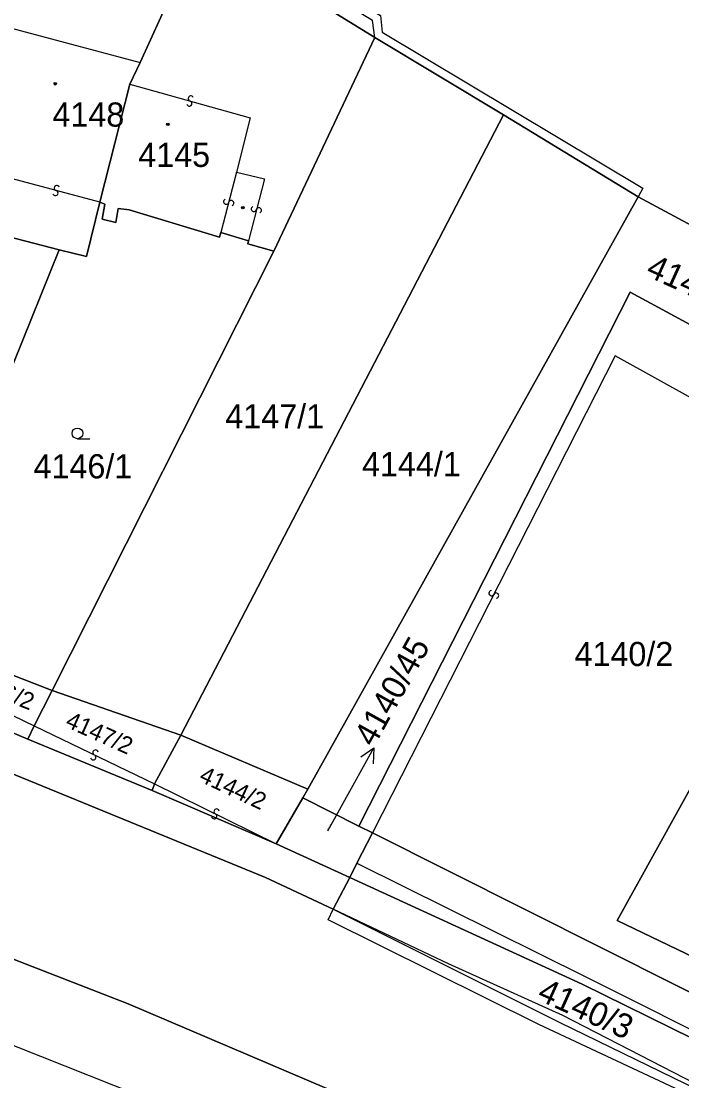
# Model space of a CAD drawing. Extents: x -598233 to -596890, y -1157848 to -1156431.
# Drawn here: x -597287.6 to -597241.1, y -1157710 to -1157635.4 of the extents above; entities that cross this region are included whole.
import ezdxf

# ---------------------------------------------------------------- set-up
doc = ezdxf.new("R2010")
doc.units = 0
for name, color, linetype in [('Level 1', 7, 'Continuous'), ('Level 13', 7, 'Continuous'), ('Level 3', 7, 'Continuous'), ('Level 4', 7, 'Continuous'), ('Level 5', 7, 'Continuous'), ('Level 57', 7, 'Continuous'), ('Level 60', 7, 'Continuous'), ('Vrstva 60', 7, 'Continuous')]:
    doc.layers.add(name, color=color, linetype=linetype)

msp = doc.modelspace()

# ---------------------------------------------------------------- linework, layer by layer
at = {"layer": 'Level 1'}
for points in [[(-597274.42, -1157629.37), (-597275.18, -1157629), (-597277.83, -1157635.13), (-597279.27, -1157638.34)], [(-597274.42, -1157629.37), (-597262.75, -1157636.58)], [(-597269.86, -1157651.62), (-597262.75, -1157636.58)], [(-597262.75, -1157636.58), (-597253.7, -1157642.01)], [(-597279.99, -1157639.86), (-597279.27, -1157638.34)], [(-597282.11, -1157648.18), (-597279.99, -1157639.86)], [(-597436.18, -1157640.9), (-597423.8, -1157643.87), (-597403.31, -1157649.2), (-597374.8, -1157657.21), (-597357.42, -1157662.9), (-597326.65, -1157673.96), (-597297.15, -1157684.79), (-597270.46, -1157695.74), (-597265.69, -1157697.96)], [(-597276.42, -1157685.7), (-597253.7, -1157642.01)], [(-597253.7, -1157642.01), (-597244.22, -1157647.79)], [(-597284.97, -1157651.52), (-597300.24, -1157647.57)], [(-597284.97, -1157651.52), (-597283.06, -1157651.99), (-597282.11, -1157648.18)], [(-597273.6, -1157650.31), (-597273.69, -1157650.63), (-597280.06, -1157648.71), (-597280.83, -1157648.62), (-597280.98, -1157649.61), (-597281.95, -1157649.36), (-597281.75, -1157648.3), (-597282.11, -1157648.18)], [(-597267.47, -1157689.5), (-597244.22, -1157647.79)], [(-597244.22, -1157647.79), (-597223.6, -1157658.88)], [(-597271.66, -1157650.89), (-597273.6, -1157650.31)], [(-597269.86, -1157651.62), (-597271.69, -1157651.11), (-597271.66, -1157650.89)], [(-597291.44, -1157667.49), (-597284.97, -1157651.52)], [(-597285.48, -1157682.57), (-597269.86, -1157651.62)], [(-597226.62, -1157664.34), (-597244.78, -1157654.52), (-597263.89, -1157692.11)], [(-597228.87, -1157668.41), (-597245.7, -1157698.76), (-597224.61, -1157708.91)], [(-597285.48, -1157682.57), (-597292.8, -1157679.73)], [(-597286.73, -1157685.05), (-597285.48, -1157682.57)], [(-597276.42, -1157685.7), (-597285.48, -1157682.57)], [(-597287.17, -1157685.98), (-597294.12, -1157683.06)], [(-597287.17, -1157685.98), (-597286.73, -1157685.05)], [(-597278.26, -1157689.14), (-597276.42, -1157685.7)], [(-597267.47, -1157689.5), (-597276.42, -1157685.7)], [(-597278.44, -1157689.6), (-597287.17, -1157685.98)], [(-597206.41, -1157739.84), (-597260.41, -1157713.03), (-597280.11, -1157704.64), (-597306.45, -1157694.39), (-597321.34, -1157688.54)], [(-597278.44, -1157689.6), (-597278.26, -1157689.14)], [(-597267.83, -1157690.13), (-597267.47, -1157689.5)], [(-597269.69, -1157693.35), (-597278.44, -1157689.6)], [(-597269.69, -1157693.35), (-597267.83, -1157690.13)], [(-597267.83, -1157690.13), (-597263.89, -1157692.11)], [(-597263.89, -1157692.11), (-597262.93, -1157692.59)], [(-597262.93, -1157692.59), (-597264.02, -1157694.72)], [(-597262.93, -1157692.59), (-597203.85, -1157722.25)], [(-597323.49, -1157693.63), (-597308.23, -1157699.6), (-597274.42, -1157713.03), (-597265.13, -1157717.22)], [(-597264.52, -1157695.72), (-597269.69, -1157693.35)], [(-597264.02, -1157694.72), (-597264.52, -1157695.72)], [(-597265.69, -1157697.96), (-597264.52, -1157695.72)], [(-597264.52, -1157695.72), (-597248.17, -1157703.24), (-597226.43, -1157713.96), (-597204.86, -1157724.29)], [(-597203.17, -1157729.43), (-597220.64, -1157720.4), (-597251.21, -1157706.08), (-597266.03, -1157698.72), (-597265.69, -1157697.96)]]:
    msp.add_lwpolyline(points, dxfattribs=at)
at = {"layer": 'Level 13'}
for centre, start, end in [((-597275.708, -1157640.873), 21.66017, 253.75817), ((-597275.811, -1157641.227), 201.44572, 74.03572), ((-597285.24, -1157647.528), 202.2675, 74.3655), ((-597285.141, -1157647.173), 22.05304, 254.64304), ((-597273.218, -1157648.133), 112.55383, 345.14383), ((-597272.862, -1157648.228), 292.76829, 164.86628), ((-597271.278, -1157648.653), 112.66023, 345.25023), ((-597270.922, -1157648.748), 292.87469, 164.97268), ((-597254.544, -1157675.706), 100.19898, 332.78898), ((-597254.216, -1157675.875), 280.41344, 152.51143), ((-597282.581, -1157687.265), 191.38328, 63.97328), ((-597282.418, -1157686.935), 11.59773, 243.69573), ((-597273.897, -1157691.085), 11.21022, 243.30822), ((-597274.062, -1157691.415), 190.99577, 63.58577)]:
    msp.add_arc(centre, 0.184, start, end, dxfattribs=at)
at = {"layer": 'Level 3'}
for points in [[(-597287.53, -1157622.17), (-597303.98, -1157613.97), (-597304.26, -1157614.64), (-597304.71, -1157614.38), (-597304.16, -1157613.27), (-597287.27, -1157621.7), (-597286.54, -1157620.31), (-597262.36, -1157635.02), (-597262.23, -1157636.2), (-597243.89, -1157647.18), (-597244.22, -1157647.79)], [(-597262.75, -1157636.58), (-597262.93, -1157635.38), (-597274.03, -1157628.64)], [(-597289.97, -1157646.1), (-597290.84, -1157645.84), (-597288.32, -1157635.92), (-597279.27, -1157638.34)], [(-597279.99, -1157639.86), (-597271.53, -1157642.24), (-597272.49, -1157646.05)], [(-597272.49, -1157646.05), (-597273.6, -1157650.31)], [(-597272.49, -1157646.05), (-597270.53, -1157646.52), (-597271.66, -1157650.89)], [(-597282.11, -1157648.18), (-597288.26, -1157646.52)], [(-597228.87, -1157668.41), (-597245.84, -1157658.99), (-597262.93, -1157692.59)], [(-597293.58, -1157681.74), (-597286.73, -1157685.05)], [(-597286.73, -1157685.05), (-597278.26, -1157689.14)], [(-597278.26, -1157689.14), (-597269.69, -1157693.35)], [(-597264.02, -1157694.72), (-597247.9, -1157702.73), (-597204.86, -1157724.29)], [(-597228.48, -1157716.29), (-597249.52, -1157705.44), (-597257.57, -1157701.81), (-597265.69, -1157697.96)], [(-597265.69, -1157697.96), (-597249.74, -1157705.94), (-597228.48, -1157716.29)]]:
    msp.add_lwpolyline(points, dxfattribs=at)
at = {"layer": 'Level 5'}
msp.add_line((-597283.69, -1157664.83), (-597282.815, -1157664.83), dxfattribs=at)
for centre, radius in [((-597285.25, -1157639.83), 0.09), ((-597285.25, -1157639.83), 0.0521), ((-597277.33, -1157642.69), 0.09), ((-597277.33, -1157642.69), 0.0521), ((-597272.05, -1157648.56), 0.09), ((-597272.05, -1157648.56), 0.0521), ((-597283.69, -1157664.455), 0.375)]:
    msp.add_circle(centre, radius, dxfattribs=at)
at = {"layer": 'Level 57'}
for p, q in [((-597264.282, -1157689.234), (-597262.827, -1157686.611)), ((-597266.06, -1157692.44), (-597264.282, -1157689.234))]:
    msp.add_line(p, q, dxfattribs=at)
msp.add_lwpolyline([(-597263.749, -1157687.242), (-597262.827, -1157686.611), (-597262.875, -1157687.728)], dxfattribs=at)
at = {"layer": 'Level 60'}
for points in [[(-597105.48, -1157726.35), (-597142.21, -1157703.35), (-597142.63, -1157703.09), (-597163.36, -1157691.81), (-597183.34, -1157680.94), (-597203.62, -1157669.9), (-597204.01, -1157669.69), (-597223.6, -1157658.88), (-597244.22, -1157647.79), (-597253.7, -1157642.01), (-597262.75, -1157636.58), (-597274.42, -1157629.37), (-597274.03, -1157628.64), (-597275.33, -1157627.77), (-597275.92, -1157628.88), (-597286.84, -1157621.88), (-597287.53, -1157622.17), (-597287.76, -1157622.64), (-597288.14, -1157622.45), (-597304.52, -1157615.14), (-597305.39, -1157615), (-597306.09, -1157615.82), (-597336.02, -1157596.93), (-597343.31, -1157592.43)], [(-597356.03, -1157660.15), (-597325.9, -1157671.16), (-597312.06, -1157676.28), (-597298.62, -1157681.23), (-597297.23, -1157681.78), (-597294.12, -1157683.06), (-597287.17, -1157685.98), (-597278.44, -1157689.6), (-597269.69, -1157693.35), (-597264.52, -1157695.72), (-597265.69, -1157697.96), (-597270.46, -1157695.74), (-597297.15, -1157684.79), (-597326.65, -1157673.96), (-597357.42, -1157662.9)]]:
    msp.add_lwpolyline(points, dxfattribs=at)
for points in [[(-597274.42, -1157629.37), (-597275.18, -1157629), (-597277.83, -1157635.13), (-597279.27, -1157638.34), (-597279.99, -1157639.86), (-597282.11, -1157648.18), (-597283.06, -1157651.99), (-597284.97, -1157651.52), (-597300.24, -1157647.57), (-597292.3, -1157628.34), (-597291.08, -1157628.87), (-597288.38, -1157622.79), (-597288.14, -1157622.45), (-597287.76, -1157622.64), (-597287.53, -1157622.17), (-597286.84, -1157621.88), (-597275.92, -1157628.88), (-597275.33, -1157627.77), (-597274.03, -1157628.64)], [(-597262.75, -1157636.58), (-597269.86, -1157651.62), (-597271.69, -1157651.11), (-597271.66, -1157650.89), (-597273.6, -1157650.31), (-597273.69, -1157650.63), (-597280.06, -1157648.71), (-597280.83, -1157648.62), (-597280.98, -1157649.61), (-597281.95, -1157649.36), (-597281.75, -1157648.3), (-597282.11, -1157648.18), (-597279.99, -1157639.86), (-597279.27, -1157638.34), (-597277.83, -1157635.13), (-597275.18, -1157629), (-597274.42, -1157629.37)], [(-597253.7, -1157642.01), (-597276.42, -1157685.7), (-597285.48, -1157682.57), (-597269.86, -1157651.62), (-597262.75, -1157636.58)], [(-597244.22, -1157647.79), (-597267.47, -1157689.5), (-597276.42, -1157685.7), (-597253.7, -1157642.01)], [(-597284.97, -1157651.52), (-597291.44, -1157667.49), (-597291.61, -1157667.24), (-597293.49, -1157669.57), (-597294.74, -1157672.51), (-597295.44, -1157674.7), (-597298.57, -1157671.87), (-597303.64, -1157669.17), (-597306.37, -1157674.04), (-597310.49, -1157672.49), (-597300.24, -1157647.57)], [(-597269.86, -1157651.62), (-597285.48, -1157682.57), (-597292.8, -1157679.73), (-597295.87, -1157678.53), (-597295.68, -1157678.06), (-597291.44, -1157667.49), (-597284.97, -1157651.52), (-597283.06, -1157651.99), (-597282.11, -1157648.18), (-597281.75, -1157648.3), (-597281.95, -1157649.36), (-597280.98, -1157649.61), (-597280.83, -1157648.62), (-597280.06, -1157648.71), (-597273.69, -1157650.63), (-597273.6, -1157650.31), (-597271.66, -1157650.89), (-597271.69, -1157651.11)], [(-597244.22, -1157647.79), (-597223.6, -1157658.88), (-597226.62, -1157664.34), (-597244.78, -1157654.52), (-597263.89, -1157692.11), (-597267.83, -1157690.13), (-597267.47, -1157689.5)], [(-597244.78, -1157654.52), (-597226.62, -1157664.34), (-597228.87, -1157668.41), (-597245.7, -1157698.76), (-597224.61, -1157708.91), (-597223.9, -1157709.25), (-597223.46, -1157708.39), (-597202.15, -1157718.82), (-597203.85, -1157722.25), (-597262.93, -1157692.59), (-597263.89, -1157692.11)], [(-597245.7, -1157698.76), (-597228.87, -1157668.41), (-597226.62, -1157664.34), (-597206.82, -1157675.05), (-597209.1, -1157679.38), (-597224.61, -1157708.91)], [(-597286.73, -1157685.05), (-597287.17, -1157685.98), (-597294.12, -1157683.06), (-597297.23, -1157681.78), (-597295.87, -1157678.53), (-597292.8, -1157679.73), (-597285.48, -1157682.57)], [(-597278.26, -1157689.14), (-597278.44, -1157689.6), (-597287.17, -1157685.98), (-597286.73, -1157685.05), (-597285.48, -1157682.57), (-597276.42, -1157685.7)], [(-597276.42, -1157685.7), (-597267.47, -1157689.5), (-597267.83, -1157690.13), (-597269.69, -1157693.35), (-597278.44, -1157689.6), (-597278.26, -1157689.14)], [(-597263.89, -1157692.11), (-597262.93, -1157692.59), (-597264.02, -1157694.72), (-597264.52, -1157695.72), (-597269.69, -1157693.35), (-597267.83, -1157690.13)], [(-597248.17, -1157703.24), (-597264.52, -1157695.72), (-597264.02, -1157694.72), (-597262.93, -1157692.59), (-597203.85, -1157722.25), (-597204.86, -1157724.29), (-597226.43, -1157713.96)], [(-597308.23, -1157699.6), (-597274.42, -1157713.03), (-597265.13, -1157717.22), (-597266.49, -1157735.43), (-597266.77, -1157739.16), (-597271.23, -1157798.83), (-597271.44, -1157801.64), (-597271.69, -1157804.95), (-597272.23, -1157804.82), (-597267.63, -1157744.82), (-597279.67, -1157743.88), (-597284.24, -1157803.9), (-597302.09, -1157802.66), (-597301.45, -1157792.4), (-597337.11, -1157790.23), (-597333.99, -1157744.43), (-597331.01, -1157701.76), (-597330.83, -1157696.39), (-597329.58, -1157696.52), (-597323.49, -1157693.63)], [(-597200.42, -1157730.59), (-597203.17, -1157729.43), (-597220.64, -1157720.4), (-597251.21, -1157706.08), (-597266.03, -1157698.72), (-597265.69, -1157697.96), (-597264.52, -1157695.72), (-597248.17, -1157703.24), (-597226.43, -1157713.96), (-597204.86, -1157724.29), (-597201.45, -1157726), (-597196.19, -1157729.11), (-597196.52, -1157729.66), (-597196.97, -1157730.19), (-597197.74, -1157730.69), (-597198.63, -1157730.94), (-597199.55, -1157730.91)]]:
    msp.add_lwpolyline(points, close=True, dxfattribs=at)
at = {"layer": 'Vrstva 60'}
for points in [[(-597117.85, -1157772.55), (-597172.78, -1157744.55), (-597189.92, -1157735.64), (-597200.42, -1157730.59), (-597203.17, -1157729.43), (-597220.64, -1157720.4), (-597251.21, -1157706.08), (-597266.03, -1157698.72), (-597265.69, -1157697.96), (-597270.46, -1157695.74), (-597297.15, -1157684.79), (-597326.65, -1157673.96), (-597357.42, -1157662.9), (-597374.8, -1157657.21), (-597403.31, -1157649.2), (-597423.8, -1157643.87), (-597436.18, -1157640.9), (-597457.3, -1157637.23), (-597508.21, -1157627.05), (-597565.01, -1157615.5), (-597619.03, -1157604.22), (-597671.31, -1157593.83)], [(-597674.27, -1157604.65), (-597621.93, -1157615.29), (-597566.92, -1157626.51), (-597510.31, -1157637.9), (-597457.99, -1157648.3), (-597439.97, -1157652.08), (-597390.15, -1157664.59), (-597337.71, -1157682.1), (-597321.34, -1157688.54), (-597306.45, -1157694.39), (-597280.11, -1157704.64), (-597260.41, -1157713.03), (-597206.41, -1157739.84), (-597194.09, -1157745.8), (-597142.37, -1157771.55), (-597092.94, -1157796.34)], [(-597092.94, -1157796.34), (-597142.37, -1157771.55), (-597194.09, -1157745.8), (-597206.41, -1157739.84), (-597260.41, -1157713.03), (-597280.11, -1157704.64), (-597306.45, -1157694.39), (-597321.34, -1157688.54), (-597337.71, -1157682.1), (-597390.15, -1157664.59), (-597439.97, -1157652.08), (-597457.99, -1157648.3), (-597510.31, -1157637.9), (-597566.92, -1157626.51), (-597621.93, -1157615.29), (-597674.27, -1157604.65)], [(-597453.17, -1157654.48), (-597446.51, -1157656.23), (-597412.77, -1157664.74), (-597383.36, -1157672.54), (-597379.43, -1157673.81), (-597374.36, -1157675.49), (-597370.47, -1157676.78), (-597370.39, -1157675.84), (-597359.84, -1157679.31), (-597348.25, -1157683.38), (-597347.44, -1157684.71), (-597337.67, -1157688.07), (-597337.24, -1157688.24), (-597327.21, -1157692.17), (-597323.49, -1157693.63), (-597308.23, -1157699.6), (-597274.42, -1157713.03), (-597265.13, -1157717.22), (-597259.96, -1157719.55), (-597205.92, -1157746.65), (-597200.4, -1157749.35), (-597146.9, -1157775.78), (-597141.19, -1157778.61), (-597090.18, -1157803.96)]]:
    msp.add_lwpolyline(points, dxfattribs=at)

# ---------------------------------------------------------------- texts
at = {"layer": 'Level 4'}
for s, p in [('4148', (-597285.45, -1157642.85)), ('4145', (-597279.41, -1157645.69)), ('4147/1', (-597273.28, -1157664.1)), ('4146/1', (-597286.78, -1157667.62)), ('4144/1', (-597263.66, -1157667.47)), ('4140/2', (-597248.7, -1157680.84))]:
    msp.add_text(s, height=1.7, dxfattribs=at).set_placement(p)
for s, height, rotation, p in [('4140/1', 1.7, 335.7, (-597243.76, -1157653.33)), ('4146/2', 1.2, 338.4, (-597291.591, -1157682.167)), ('4147/2', 1.2, 335.7, (-597284.614, -1157685.083)), ('4144/2', 1.2, 334.8, (-597275.201, -1157688.918)), ('4140/45', 0.1, 60.86385, (-597266.06, -1157692.44)), ('4140/3', 1.7, 335.7, (-597251.41, -1157704.31))]:
    msp.add_text(s, height=height, rotation=rotation, dxfattribs=at).set_placement(p)
at = {"layer": 'Level 57'}
msp.add_text('4140/45', height=1.7, rotation=60.86385, dxfattribs=at).set_placement((-597262.827, -1157686.611))

doc.saveas('drawing.dxf')
